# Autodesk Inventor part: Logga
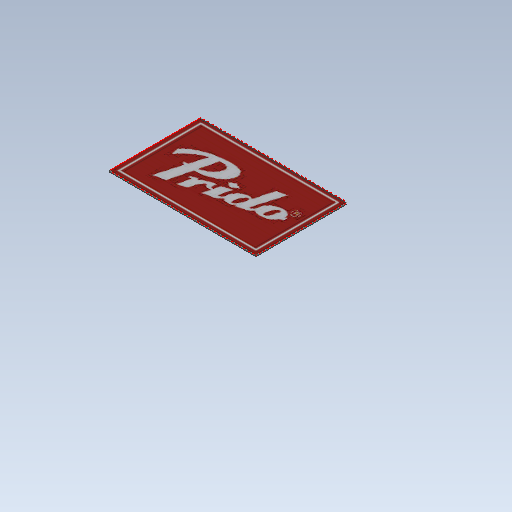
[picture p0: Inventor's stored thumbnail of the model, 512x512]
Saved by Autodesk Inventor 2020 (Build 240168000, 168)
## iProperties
Created: 2019-06
Part Number: Logga
Material: UHMW, Black
Document SubType Name: Modeling
Designer: cl
Density: 0.94 g/cm^3
Appearance: Smooth - Black
Author: cl
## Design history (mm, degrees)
sketch "Sketch3"
  geometry: L1 (0, 0)-(130, 0); L2 (130, 0)-(130, -80); L3 (130, -80)-(0, -80); L4 (0, -80)-(0, 0)
  constraints: 8 end point, 2 parallel, 1 horizontal, 1 perpendicular
  dimensions: "d8" = 130 distance of L2.end L3.end; "d9" = 80 distance of L1.end L2.end
extrude "Extrusion1" new body sketch "Sketch3" distance "d10" = 1; taper "d11" = 0 deg
sketch "Sketch5" dims "d8" = 130
  geometry: L1 (-130, 81.24)-(0, 81.24); L2 (0, 81.24)-(0, 0); L3 (0, 0)-(-130, 0); L4 (-130, 0)-(-130, 81.24); L5 (-130, 80)-(-130, 0) reference; 1 other entity
  constraints: 1 collinear, 2 other
  node "Image3"
body "Solid1"
